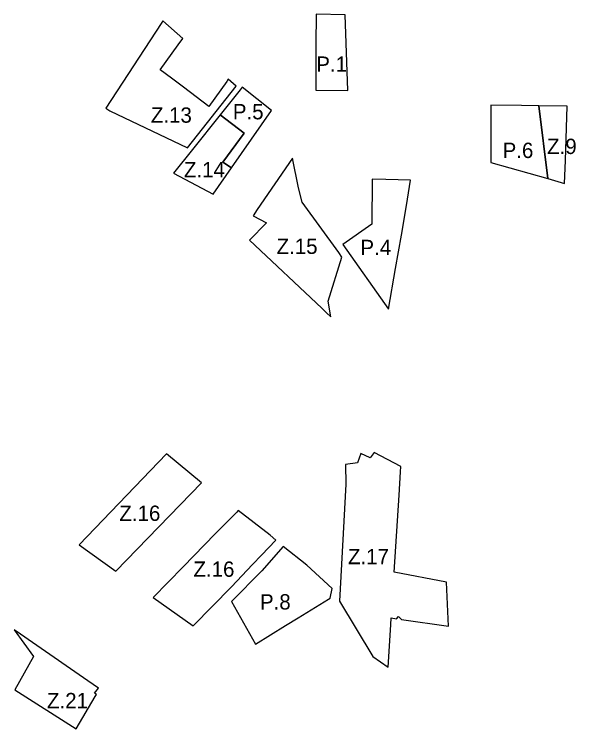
# Model space of a CAD drawing. Extents: x -438701 to -435614, y -1126017 to -1121766.
# Drawn here: x -438701 to -438334.6, y -1124058.9 to -1123592.5 of the extents above; entities that cross this region are included whole.
import ezdxf

# ---------------------------------------------------------------- set-up
doc = ezdxf.new("R2010")
doc.units = 0
for name, color, linetype in [('NAVRH', 7, 'Continuous'), ('STAV', 7, 'Continuous'), ('Vrstva 3', 7, 'Continuous'), ('Vrstva 6', 7, 'Continuous'), ('Vrstva 7', 7, 'Continuous'), ('Vrstva 9', 7, 'Continuous')]:
    doc.layers.add(name, color=color, linetype=linetype)

msp = doc.modelspace()

# ---------------------------------------------------------------- linework, layer by layer
at = {"layer": 'NAVRH'}
for p, q in [((-438605.14, -1123598.39), (-438641.13, -1123653.65)), ((-438604.01, -1123596.66), (-438605.14, -1123598.39)), ((-438590.97, -1123608.31), (-438604.01, -1123596.66)), ((-438594.06, -1123612.41), (-438590.97, -1123608.31)), ((-438605.68, -1123628.72), (-438594.06, -1123612.41)), ((-438598.33, -1123634.23), (-438605.68, -1123628.72)), ((-438590.62, -1123640.11), (-438598.33, -1123634.23)), ((-438556.13, -1123639.43), (-438561.27, -1123634.84)), ((-438573.93, -1123652.57), (-438590.62, -1123640.11)), ((-438587.9, -1123679.55), (-438556.13, -1123639.43)), ((-438641.13, -1123653.65), (-438638.51, -1123655.49)), ((-438638.51, -1123655.49), (-438587.9, -1123679.55)), ((-438358.55, -1123652.29), (-438352.74, -1123699.77)), ((-438550.85, -1123670.11), (-438566.56, -1123658.17)), ((-438519.48, -1123686.41), (-438542.38, -1123719.98)), ((-438515.45, -1123705.77), (-438519.48, -1123686.41)), ((-438513.04, -1123715.06), (-438515.45, -1123705.77)), ((-438489.24, -1123748.07), (-438513.04, -1123715.06)), ((-438542.38, -1123719.98), (-438545.1, -1123723.96)), ((-438547.35, -1123739.96), (-438500.33, -1123784.39)), ((-438487.18, -1123750.92), (-438489.24, -1123748.07)), ((-438500.33, -1123784.39), (-438497.37, -1123787.19)), ((-438497.37, -1123787.19), (-438494.47, -1123789.93)), ((-438601.64, -1123879.38), (-438658.72, -1123938.82)), ((-438578.69, -1123898.35), (-438601.64, -1123879.38)), ((-438466.17, -1123878.65), (-438468.66, -1123882.09)), ((-438448.59, -1123887.73), (-438466.17, -1123878.65)), ((-438476.94, -1123885.25), (-438484.83, -1123886.28)), ((-438484.83, -1123886.28), (-438484.51, -1123899.32)), ((-438448.81, -1123891.13), (-438448.59, -1123887.73)), ((-438634.58, -1123956.01), (-438578.69, -1123898.35)), ((-438484.51, -1123899.32), (-438488.65, -1123975.66)), ((-438555.8, -1123917.41), (-438569.75, -1123931.7)), ((-438554.82, -1123916.41), (-438555.8, -1123917.41)), ((-438533.95, -1123932.49), (-438554.82, -1123916.41)), ((-438569.75, -1123931.7), (-438583.74, -1123945.96)), ((-438539.62, -1123945.48), (-438530.24, -1123935.7)), ((-438530.24, -1123935.7), (-438533.95, -1123932.49)), ((-438658.72, -1123938.82), (-438634.58, -1123956.01)), ((-438545.45, -1123951.56), (-438539.62, -1123945.48)), ((-438583.74, -1123945.96), (-438590.68, -1123953.09)), ((-438590.68, -1123953.09), (-438610.3, -1123973.23)), ((-438559.28, -1123966.14), (-438545.45, -1123951.56)), ((-438418.85, -1123963.21), (-438453.03, -1123956.73)), ((-438417.58, -1123991.98), (-438418.85, -1123963.21)), ((-438584.23, -1123991.6), (-438559.28, -1123966.14)), ((-438610.3, -1123973.23), (-438584.23, -1123991.6)), ((-438488.65, -1123975.66), (-438467.06, -1124011.66)), ((-438454.94, -1123986.52), (-438451.48, -1123987.03)), ((-438451.48, -1123987.03), (-438450.2, -1123985.67)), ((-438450.2, -1123985.67), (-438448.26, -1123987.5)), ((-438448.26, -1123987.5), (-438417.58, -1123991.98)), ((-438696.9, -1123997.09), (-438700.95, -1123994.28)), ((-438700.95, -1123994.28), (-438688.33, -1124011.77)), ((-438688.97, -1124002.59), (-438696.9, -1123997.09)), ((-438652.99, -1124027.54), (-438688.97, -1124002.59)), ((-438688.33, -1124011.77), (-438700.56, -1124033.53)), ((-438467.06, -1124011.66), (-438457.01, -1124018.66)), ((-438645.98, -1124032.4), (-438652.99, -1124027.54)), ((-438700.56, -1124033.53), (-438660.48, -1124058.86)), ((-438648.5, -1124035.7), (-438645.98, -1124032.4)), ((-438660.48, -1124058.86), (-438648.22, -1124037.78)), ((-438647.32, -1124036.6), (-438648.5, -1124035.7)), ((-438648.22, -1124037.78), (-438647.32, -1124036.6))]:
    msp.add_line(p, q, dxfattribs=at)
for points in [[(-438561.27, -1123634.84), (-438562.31, -1123636.25), (-438573.93, -1123652.57)], [(-438352.74, -1123699.77), (-438341.77, -1123702.87), (-438341.26, -1123687.98), (-438340.04, -1123652.37), (-438358.55, -1123652.29)], [(-438566.56, -1123658.17), (-438584.64, -1123680.75), (-438597.02, -1123696.21), (-438571.21, -1123710), (-438559.12, -1123692.65)], [(-438559.12, -1123692.65), (-438564.79, -1123688.93), (-438550.85, -1123670.11)], [(-438545.1, -1123723.96), (-438536.42, -1123728.6), (-438547.35, -1123739.96)], [(-438494.47, -1123789.93), (-438496.01, -1123779.72), (-438487.18, -1123750.92)], [(-438468.66, -1123882.09), (-438474.82, -1123879.28), (-438476.94, -1123885.25)], [(-438453.03, -1123956.73), (-438449.79, -1123906.44), (-438448.81, -1123891.13)], [(-438457.01, -1124018.66), (-438455.23, -1123991), (-438454.94, -1123986.52)]]:
    msp.add_lwpolyline(points, dxfattribs=at)
at = {"layer": 'Vrstva 3'}
for p, q in [((-438503.9, -1123592.47), (-438504.24, -1123612.11)), ((-438485.03, -1123592.79), (-438503.9, -1123592.47)), ((-438483.19, -1123642.24), (-438485.03, -1123592.79)), ((-438504.24, -1123612.11), (-438504.19, -1123642.04)), ((-438504.19, -1123642.04), (-438483.19, -1123642.24)), ((-438566.56, -1123658.17), (-438550.85, -1123670.11)), ((-438467.4, -1123700.01), (-438467.65, -1123729.42)), ((-438467.65, -1123729.42), (-438486.6, -1123742.86)), ((-438486.6, -1123742.86), (-438456.64, -1123785.05)), ((-438525.49, -1123939.94), (-438539.35, -1123955.76)), ((-438510.07, -1123952.1), (-438525.49, -1123939.94)), ((-438493.54, -1123967.38), (-438510.07, -1123952.1)), ((-438539.35, -1123955.76), (-438559.16, -1123975.88)), ((-438494.83, -1123973.57), (-438493.54, -1123967.38))]:
    msp.add_line(p, q, dxfattribs=at)
for points in [[(-438550.85, -1123670.11), (-438564.79, -1123688.93), (-438559.12, -1123692.65), (-438533.02, -1123655.22), (-438552.19, -1123640.13), (-438553.46, -1123641.81), (-438566.56, -1123658.17)], [(-438358.55, -1123652.29), (-438370, -1123652.07), (-438389.9, -1123651.69), (-438389.9, -1123682.75), (-438389.9, -1123683.97), (-438389.9, -1123689.26), (-438352.74, -1123699.77), (-438358.55, -1123652.29)], [(-438456.64, -1123785.05), (-438452.06, -1123758.44), (-438448.29, -1123736.6), (-438444.96, -1123717.25), (-438442.41, -1123700.7), (-438458.4, -1123700.26), (-438467.4, -1123700.01)], [(-438559.16, -1123975.88), (-438543.44, -1124003.58), (-438523.97, -1123991.56)], [(-438523.97, -1123991.56), (-438515.62, -1123986.4), (-438495.91, -1123974.24), (-438494.83, -1123973.57)]]:
    msp.add_lwpolyline(points, dxfattribs=at)
at = {"layer": 'Vrstva 6'}
for p, q in [((-438605.14, -1123598.39), (-438641.13, -1123653.65)), ((-438604.01, -1123596.66), (-438605.14, -1123598.39)), ((-438590.97, -1123608.31), (-438604.01, -1123596.66)), ((-438594.06, -1123612.41), (-438590.97, -1123608.31)), ((-438605.68, -1123628.72), (-438594.06, -1123612.41)), ((-438598.33, -1123634.23), (-438605.68, -1123628.72)), ((-438590.62, -1123640.11), (-438598.33, -1123634.23)), ((-438556.13, -1123639.43), (-438561.27, -1123634.84)), ((-438573.93, -1123652.57), (-438590.62, -1123640.11)), ((-438587.9, -1123679.55), (-438556.13, -1123639.43)), ((-438641.13, -1123653.65), (-438638.51, -1123655.49)), ((-438638.51, -1123655.49), (-438587.9, -1123679.55)), ((-438358.55, -1123652.29), (-438352.74, -1123699.77)), ((-438550.85, -1123670.11), (-438566.56, -1123658.17)), ((-438519.48, -1123686.41), (-438542.38, -1123719.98)), ((-438515.45, -1123705.77), (-438519.48, -1123686.41)), ((-438513.04, -1123715.06), (-438515.45, -1123705.77)), ((-438489.24, -1123748.07), (-438513.04, -1123715.06)), ((-438542.38, -1123719.98), (-438545.1, -1123723.96)), ((-438547.35, -1123739.96), (-438500.33, -1123784.39)), ((-438487.18, -1123750.92), (-438489.24, -1123748.07)), ((-438500.33, -1123784.39), (-438497.37, -1123787.19)), ((-438497.37, -1123787.19), (-438494.47, -1123789.93)), ((-438601.64, -1123879.38), (-438658.72, -1123938.82)), ((-438578.69, -1123898.35), (-438601.64, -1123879.38)), ((-438466.17, -1123878.65), (-438468.66, -1123882.09)), ((-438448.59, -1123887.73), (-438466.17, -1123878.65)), ((-438476.94, -1123885.25), (-438484.83, -1123886.28)), ((-438484.83, -1123886.28), (-438484.51, -1123899.32)), ((-438448.81, -1123891.13), (-438448.59, -1123887.73)), ((-438634.58, -1123956.01), (-438578.69, -1123898.35)), ((-438484.51, -1123899.32), (-438488.65, -1123975.66)), ((-438555.8, -1123917.41), (-438569.75, -1123931.7)), ((-438554.82, -1123916.41), (-438555.8, -1123917.41)), ((-438533.95, -1123932.49), (-438554.82, -1123916.41)), ((-438569.75, -1123931.7), (-438583.74, -1123945.96)), ((-438539.62, -1123945.48), (-438530.24, -1123935.7)), ((-438530.24, -1123935.7), (-438533.95, -1123932.49)), ((-438658.72, -1123938.82), (-438634.58, -1123956.01)), ((-438545.45, -1123951.56), (-438539.62, -1123945.48)), ((-438583.74, -1123945.96), (-438590.68, -1123953.09)), ((-438590.68, -1123953.09), (-438610.3, -1123973.23)), ((-438559.28, -1123966.14), (-438545.45, -1123951.56)), ((-438418.85, -1123963.21), (-438453.03, -1123956.73)), ((-438417.58, -1123991.98), (-438418.85, -1123963.21)), ((-438584.23, -1123991.6), (-438559.28, -1123966.14)), ((-438610.3, -1123973.23), (-438584.23, -1123991.6)), ((-438488.65, -1123975.66), (-438467.06, -1124011.66)), ((-438454.94, -1123986.52), (-438451.48, -1123987.03)), ((-438451.48, -1123987.03), (-438450.2, -1123985.67)), ((-438450.2, -1123985.67), (-438448.26, -1123987.5)), ((-438448.26, -1123987.5), (-438417.58, -1123991.98)), ((-438696.9, -1123997.09), (-438700.95, -1123994.28)), ((-438700.95, -1123994.28), (-438688.33, -1124011.77)), ((-438688.97, -1124002.59), (-438696.9, -1123997.09)), ((-438652.99, -1124027.54), (-438688.97, -1124002.59)), ((-438688.33, -1124011.77), (-438700.56, -1124033.53)), ((-438467.06, -1124011.66), (-438457.01, -1124018.66)), ((-438645.98, -1124032.4), (-438652.99, -1124027.54)), ((-438700.56, -1124033.53), (-438660.48, -1124058.86)), ((-438648.5, -1124035.7), (-438645.98, -1124032.4)), ((-438660.48, -1124058.86), (-438648.22, -1124037.78)), ((-438647.32, -1124036.6), (-438648.5, -1124035.7)), ((-438648.22, -1124037.78), (-438647.32, -1124036.6))]:
    msp.add_line(p, q, dxfattribs=at)
for points in [[(-438561.27, -1123634.84), (-438562.31, -1123636.25), (-438573.93, -1123652.57)], [(-438352.74, -1123699.77), (-438341.77, -1123702.87), (-438341.26, -1123687.98), (-438340.04, -1123652.37), (-438358.55, -1123652.29)], [(-438566.56, -1123658.17), (-438584.64, -1123680.75), (-438597.02, -1123696.21), (-438571.21, -1123710), (-438559.12, -1123692.65)], [(-438559.12, -1123692.65), (-438564.79, -1123688.93), (-438550.85, -1123670.11)], [(-438545.1, -1123723.96), (-438536.42, -1123728.6), (-438547.35, -1123739.96)], [(-438494.47, -1123789.93), (-438496.01, -1123779.72), (-438487.18, -1123750.92)], [(-438468.66, -1123882.09), (-438474.82, -1123879.28), (-438476.94, -1123885.25)], [(-438453.03, -1123956.73), (-438449.79, -1123906.44), (-438448.81, -1123891.13)], [(-438457.01, -1124018.66), (-438455.23, -1123991), (-438454.94, -1123986.52)]]:
    msp.add_lwpolyline(points, dxfattribs=at)
at = {"layer": 'Vrstva 7'}
for p, q in [((-438503.9, -1123592.47), (-438504.24, -1123612.11)), ((-438485.03, -1123592.79), (-438503.9, -1123592.47)), ((-438483.19, -1123642.24), (-438485.03, -1123592.79)), ((-438504.24, -1123612.11), (-438504.19, -1123642.04)), ((-438504.19, -1123642.04), (-438483.19, -1123642.24)), ((-438566.56, -1123658.17), (-438550.85, -1123670.11)), ((-438467.4, -1123700.01), (-438467.65, -1123729.42)), ((-438467.65, -1123729.42), (-438486.6, -1123742.86)), ((-438486.6, -1123742.86), (-438456.64, -1123785.05)), ((-438525.49, -1123939.94), (-438539.35, -1123955.76)), ((-438510.07, -1123952.1), (-438525.49, -1123939.94)), ((-438493.54, -1123967.38), (-438510.07, -1123952.1)), ((-438539.35, -1123955.76), (-438559.16, -1123975.88)), ((-438494.83, -1123973.57), (-438493.54, -1123967.38))]:
    msp.add_line(p, q, dxfattribs=at)
for points in [[(-438550.85, -1123670.11), (-438564.79, -1123688.93), (-438559.12, -1123692.65), (-438533.02, -1123655.22), (-438552.19, -1123640.13), (-438553.46, -1123641.81), (-438566.56, -1123658.17)], [(-438358.55, -1123652.29), (-438370, -1123652.07), (-438389.9, -1123651.69), (-438389.9, -1123682.75), (-438389.9, -1123683.97), (-438389.9, -1123689.26), (-438352.74, -1123699.77), (-438358.55, -1123652.29)], [(-438456.64, -1123785.05), (-438452.06, -1123758.44), (-438448.29, -1123736.6), (-438444.96, -1123717.25), (-438442.41, -1123700.7), (-438458.4, -1123700.26), (-438467.4, -1123700.01)], [(-438559.16, -1123975.88), (-438543.44, -1124003.58), (-438523.97, -1123991.56)], [(-438523.97, -1123991.56), (-438515.62, -1123986.4), (-438495.91, -1123974.24), (-438494.83, -1123973.57)]]:
    msp.add_lwpolyline(points, dxfattribs=at)

# ---------------------------------------------------------------- texts
at = {"layer": 'STAV'}
for s, p in [('P.1', (-438503.88, -1123630.02)), ('P.5', (-438558.32, -1123661.04)), ('P.6', (-438382.26, -1123686.29)), ('P.4', (-438475.08, -1123749.7)), ('P.8', (-438540.62, -1123981.05))]:
    msp.add_text(s, height=10, dxfattribs=at).set_placement(p)
at = {"layer": 'Vrstva 9'}
for s, p in [('Z.13', (-438611.83, -1123663.26)), ('Z.9', (-438353.24, -1123683.69)), ('Z.14', (-438590.25, -1123698.9)), ('Z.15', (-438529.77, -1123748.93)), ('Z.16', (-438632.38, -1123923.2)), ('Z.17', (-438483.18, -1123951.46)), ('Z.16', (-438584.03, -1123959.69)), ('Z.21', (-438679.63, -1124045.51))]:
    msp.add_text(s, height=10, dxfattribs=at).set_placement(p)

doc.saveas('drawing.dxf')
